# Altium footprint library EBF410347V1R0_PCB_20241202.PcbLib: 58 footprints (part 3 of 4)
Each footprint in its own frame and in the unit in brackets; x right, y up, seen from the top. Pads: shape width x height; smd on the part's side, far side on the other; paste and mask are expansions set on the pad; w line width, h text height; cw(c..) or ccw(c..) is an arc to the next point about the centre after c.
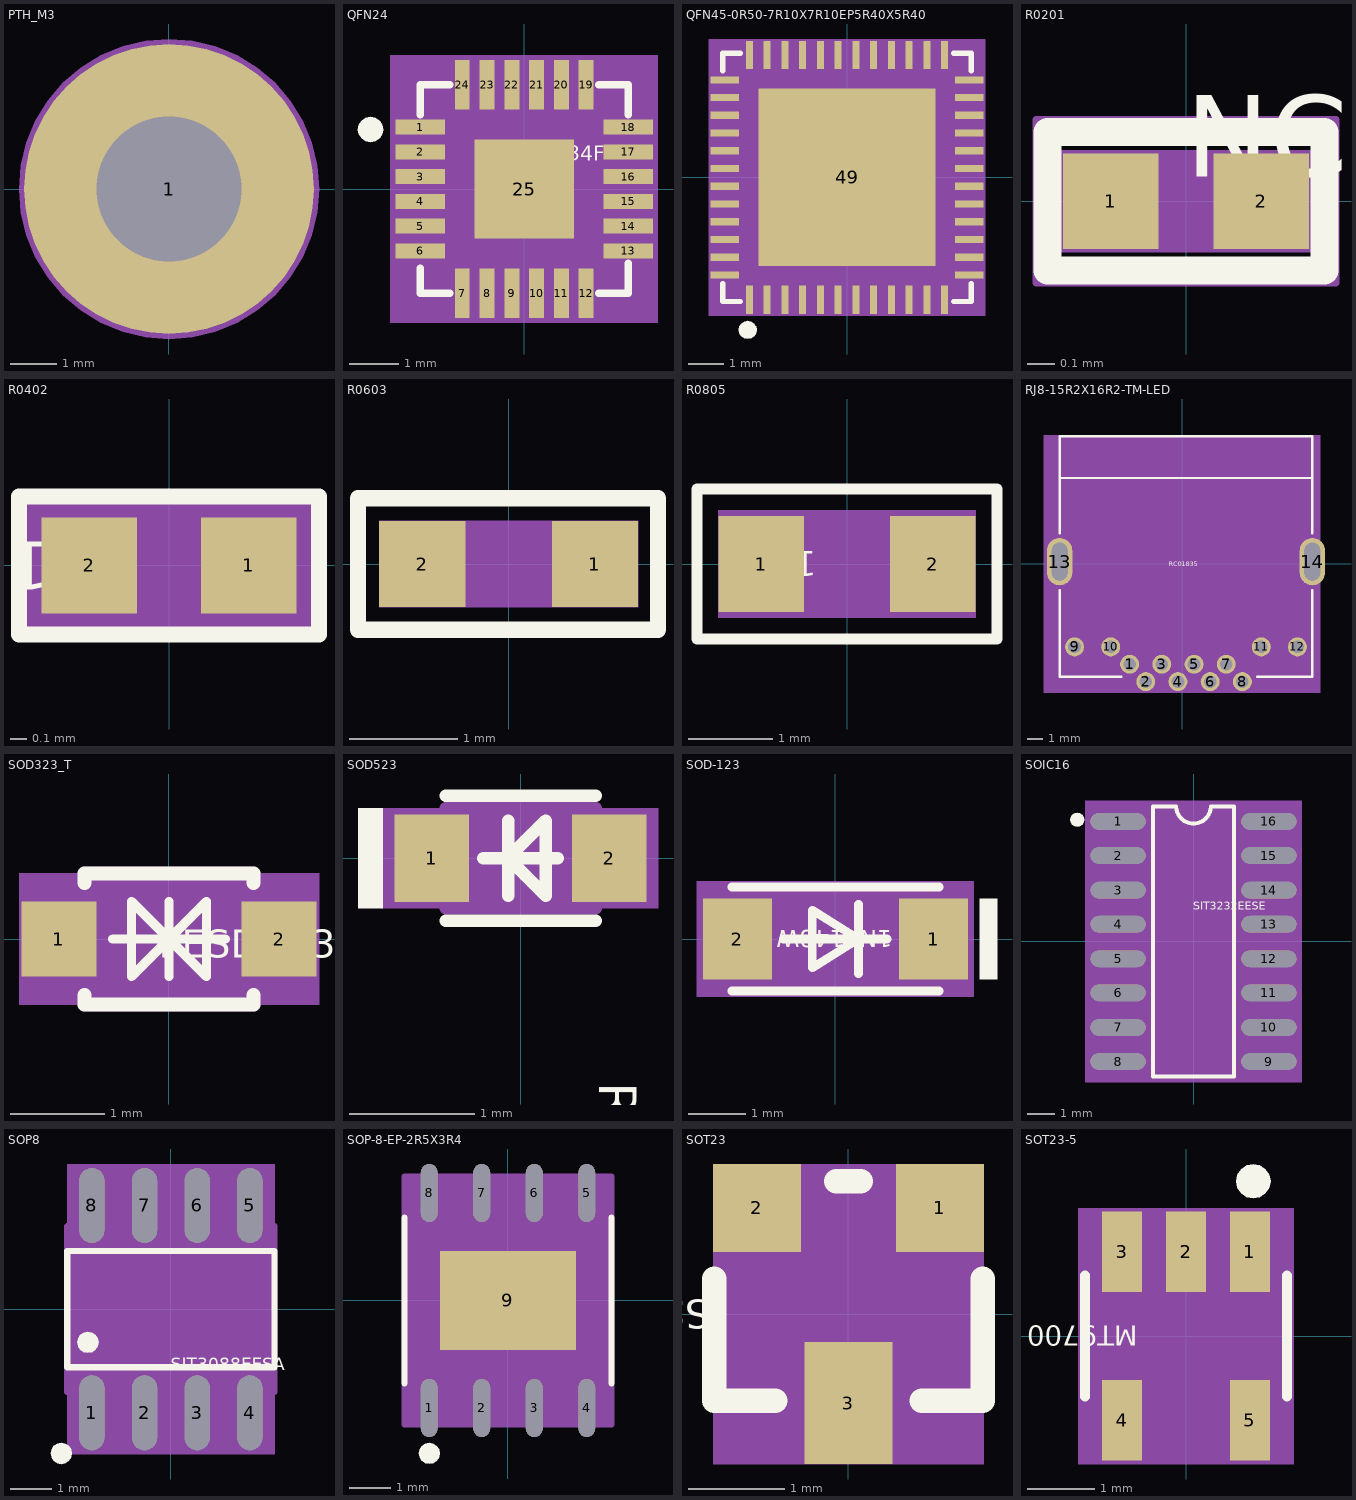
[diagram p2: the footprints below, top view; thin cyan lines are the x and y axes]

## PTH_M3 [mm] "PTH_M3"
pads (1):
  round 6.2 hole 3.1: 1(0,0)
Top Overlay:
  text "PTH_M3" at -0.72,-0.15 h0.3
Top 3D Body:
  region: 3.21,0 3.17,0.502 3.053,0.992 2.86,1.457 2.597,1.887 2.27,2.27 1.887,2.597 1.457,2.86 0.992,3.053 0.502,3.17 0,3.21 -0.502,3.17 -0.992,3.053 -1.457,2.86 -1.601,2.772 -1.887,2.597 -2.27,2.27 -2.597,1.887 -2.86,1.457 -3.053,0.992 -3.17,0.502 -3.21,0 -3.17,-0.502 -3.053,-0.992 -2.86,-1.457 -2.597,-1.887 -2.27,-2.27 -1.887,-2.597 -1.601,-2.772 -1.457,-2.86 -0.992,-3.053 -0.502,-3.17 0,-3.21 0.502,-3.17 0.992,-3.053 1.457,-2.86 1.887,-2.597 2.27,-2.27 2.597,-1.887 2.86,-1.457 3.053,-0.992 3.17,-0.502
Mechanical 14:
  text "1" at -0.254,0 h0.64
3D body: height 3.81, standoff 0, extent -3.21,-3.21 3.21,3.21

## QFN24 [mm] "QFN24"
pads (25):
  rect 1x0.3 smd: 1(-2.1,1.25) 2(-2.1,0.75) 3(-2.1,0.25) 4(-2.1,-0.25) 5(-2.1,-0.75) 6(-2.1,-1.25) 13(2.1,-1.25) 14(2.1,-0.75) 15(2.1,-0.25) 16(2.1,0.25) 17(2.1,0.75) 18(2.1,1.25)
  rect 0.3x1 smd: 7(-1.25,-2.1) 8(-0.75,-2.1) 9(-0.25,-2.1) 10(0.25,-2.1) 11(0.75,-2.1) 12(1.25,-2.1) 19(1.25,2.1) 20(0.75,2.1) 21(0.25,2.1) 22(-0.25,2.1) 23(-0.75,2.1) 24(-1.25,2.1)
  rect 2x2 smd: 25(0,0)
Top Overlay:
  dashed: -3.1,0.945 -3.002,0.965 -2.92,1.02 -2.865,1.102 -2.845,1.2 -2.865,1.298 -2.883,1.325 -2.92,1.38 -3.002,1.435 -3.1,1.455 -3.198,1.435 -3.28,1.38 -3.317,1.325 -3.335,1.298 -3.355,1.2 -3.335,1.102 -3.28,1.02 -3.198,0.965
  lines w0.15: -2.1,-1.6 -2.1,-2.1 -1.5,-2.1 ; -2.1,1.5 -2.1,2.1 -1.5,2.1 ; 1.5,-2.1 2.1,-2.1 2.1,-1.5 ; 1.5,2.1 2.1,2.1 2.1,1.5
  text "CH334F" at 0,0.57 h0.3
Top 3D Body:
  region: -2.7,-2.7 2.7,-2.7 2.7,2.7 -2.7,2.7
Mechanical 14:
  text "25" at 0,0.325 h0.41
  text "11" at 0.75,-1.775 h0.41
  text "12" at 1.25,-1.775 h0.41
  text "16" at 2.1,0.575 h0.41
  text "18" at 2.1,1.575 h0.41
  text "15" at 2.1,0.075 h0.41
  text "14" at 2.1,-0.425 h0.41
  text "6" at -2.1,-1.087 h0.41
  text "1" at -2.1,1.412 h0.41
  text "20" at 0.75,2.425 h0.41
  text "3" at -2.1,0.412 h0.41
  text "5" at -2.1,-0.588 h0.41
  text "13" at 2.1,-0.925 h0.41
  text "17" at 2.1,1.075 h0.41
  text "4" at -2.1,-0.087 h0.41
  text "7" at -1.25,-1.938 h0.41
  text "8" at -0.75,-1.938 h0.41
  text "10" at 0.25,-1.775 h0.41
  text "9" at -0.25,-1.938 h0.41
  text "19" at 1.25,2.425 h0.41
  text "2" at -2.1,0.913 h0.41
  text "24" at -1.25,2.425 h0.41
  text "23" at -0.75,2.425 h0.41
  text "22" at -0.25,2.425 h0.41
  text "21" at 0.25,2.425 h0.41
Top Assembly:
  lines w0.2: -2.05,-2.05 -2.05,2.05 2.05,2.05 2.05,-2.05 -2.05,-2.05
3D body: height 3.81, standoff 0, extent -2.7,-2.7 2.7,2.7

## QFN45-0R50-7R10X7R10EP5R40X5R40 [mm] "QFN45-0R50-7R10X7R10EP5R40X5R40"
pads (49):
  rect 0.2x0.8 smd: 1(-2.75,-3.45) 2(-2.25,-3.45) 3(-1.75,-3.45) 4(-1.25,-3.45) 5(-0.75,-3.45) 6(-0.25,-3.45) 7(0.25,-3.45) 8(0.75,-3.45) 9(1.25,-3.45) 10(1.75,-3.45) 11(2.25,-3.45) 12(2.75,-3.45) 25(2.75,3.45) 26(2.25,3.45) 27(1.75,3.45) 28(1.25,3.45) 29(0.75,3.45) 30(0.25,3.45) 31(-0.25,3.45) 32(-0.75,3.45) 33(-1.25,3.45) 34(-1.75,3.45) 35(-2.25,3.45) 36(-2.75,3.45)
  rect 0.8x0.2 smd: 13(3.45,-2.75) 14(3.45,-2.25) 15(3.45,-1.75) 16(3.45,-1.25) 17(3.45,-0.75) 18(3.45,-0.25) 19(3.45,0.25) 20(3.45,0.75) 21(3.45,1.25) 22(3.45,1.75) 23(3.45,2.25) 24(3.45,2.75) 37(-3.45,2.75) 38(-3.45,2.25) 39(-3.45,1.75) 40(-3.45,1.25) 41(-3.45,0.75) 42(-3.45,0.25) 43(-3.45,-0.25) 44(-3.45,-0.75) 45(-3.45,-1.25) 46(-3.45,-1.75) 47(-3.45,-2.25) 48(-3.45,-2.75)
  rect 5x5 smd: 49(0,0)
Top Overlay:
  dashed: -2.8,-4.555 -2.702,-4.535 -2.62,-4.48 -2.564,-4.398 -2.545,-4.3 -2.564,-4.202 -2.583,-4.175 -2.62,-4.12 -2.702,-4.064 -2.8,-4.045 -2.898,-4.064 -2.98,-4.12 -3.017,-4.175 -3.036,-4.202 -3.055,-4.3 -3.036,-4.398 -2.98,-4.48 -2.898,-4.535
  lines w0.15: -3.5,-3 -3.5,-3.5 -3,-3.5 ; -3.5,3 -3.5,3.5 -3,3.5 ; 3,-3.5 3.5,-3.5 3.5,-3 ; 3,3.5 3.5,3.5 3.5,3
  text "GM8775C" at 0,0.69 h0.3
Top 3D Body:
  region: -3.9,3.9 -3.9,-3.9 3.9,-3.9 3.9,3.9
Mechanical 14:
  text "5" at -0.75,-3.348 h0.25
  text "37" at -3.324,3.156 h0.25
  text "9" at 1.25,-3.348 h0.25
  text "49" at 0,0.203 h0.25
  text "21" at 3.576,1.656 h0.25
  text "17" at 3.576,-0.344 h0.25
  text "16" at 3.576,-0.944 h0.25
  text "43" at -3.324,0.156 h0.25
  text "12" at 2.75,-3.247 h0.25
  text "29" at 0.75,3.653 h0.25
  text "28" at 1.25,3.653 h0.25
  text "8" at 0.75,-3.348 h0.25
  text "7" at 0.25,-3.348 h0.25
  text "30" at 0.25,3.653 h0.25
  text "45" at -3.324,-0.844 h0.25
  text "15" at 3.576,-1.344 h0.25
  text "31" at -0.25,3.653 h0.25
  text "47" at -3.324,-1.944 h0.25
  text "40" at -3.324,1.556 h0.25
  text "24" at 3.576,3.056 h0.25
  text "2" at -2.25,-3.348 h0.25
  text "11" at 2.25,-3.247 h0.25
  text "32" at -0.75,3.653 h0.25
  text "25" at 2.75,3.653 h0.25
  text "14" at 3.576,-1.844 h0.25
  text "18" at 3.576,0.156 h0.25
  text "42" at -3.324,0.656 h0.25
  text "34" at -1.75,3.653 h0.25
  text "19" at 3.576,0.656 h0.25
  text "44" at -3.324,-0.344 h0.25
  text "22" at 3.576,2.056 h0.25
  text "46" at -3.324,-1.344 h0.25
  text "20" at 3.576,1.156 h0.25
  text "23" at 3.576,2.656 h0.25
  text "39" at -3.324,2.056 h0.25
  text "33" at -1.25,3.653 h0.25
  text "35" at -2.25,3.653 h0.25
  text "36" at -2.75,3.653 h0.25
  text "38" at -3.324,2.556 h0.25
  text "41" at -3.324,1.156 h0.25
  text "13" at 3.5,-2.394 h0.25
  text "10" at 1.75,-3.247 h0.25
  text "27" at 1.75,3.653 h0.25
  text "1" at -2.75,-3.348 h0.25
  text "26" at 2.25,3.653 h0.25
  text "48" at -3.324,-2.344 h0.25
  text "6" at -0.25,-3.348 h0.25
  text "4" at -1.25,-3.348 h0.25
  text "3" at -1.75,-3.348 h0.25
Top Assembly:
  lines w0.15: -3.5,-3.5 3.5,-3.5 3.5,3.5 -3.5,3.5 -3.5,-3.5
3D body: height 3.81, standoff 0, extent -3.9,-3.9 3.9,3.9

## R0201 [mm] "R0201"
pads (2):
  rect 0.35x0.35 smd: 1(-0.275,0) 2(0.275,0)
Top Overlay:
  lines w0.102: -0.508,-0.254 0.508,-0.254 0.508,0.254 -0.508,0.254 -0.508,-0.254
  text ".Designator" at 0,0.33 h0.3
  text "NC" at 0,0.09 h0.3
Top 3D Body:
  region: -0.475,-0.175 0.475,-0.175 0.475,0.175 -0.475,0.175
Mechanical 14:
  text "1" at -0.275,0.203 h0.51
  text "2" at 0.275,0.203 h0.51
Top Assembly:
  lines w0.025: -0.55,-0.3 -0.55,0.3 0.55,0.3 0.55,-0.3 -0.55,-0.3 ; -0.475,-0.175 0.475,-0.175 0.475,0.175 -0.475,0.175 -0.475,-0.175
  text "NC" at 0,0 h0.51
3D body: height 3.81, standoff 0, extent -0.475,-0.175 0.475,0.175

## R0402 [mm] "R0402"
pads (2):
  rect 0.599x0.599 smd: 1(0.5,0) 2(-0.5,0)
Top Overlay:
  lines w0.102: -0.94,-0.432 0.94,-0.432 0.94,0.432 -0.94,0.432 -0.94,-0.432
  text "115K" at -0.48,0.15 h0.3
Top 3D Body:
  region: -0.94,-0.432 -0.94,0.432 0.94,0.432 0.94,-0.432
Mechanical 14:
  text "2" at -0.957,0 h1.14
  text "1" at 0.043,0 h1.14
Top Assembly:
  dashed: 0.94,0.432 0.94,-0.432 -0.94,-0.432 -0.94,0.432
3D body: height 3.81, standoff 0, extent -0.94,-0.432 0.94,0.432

## R0603 [mil] "R0603"
pads (2):
  rect 31.5x31.5 smd: 1(31.5,0) 2(-31.5,0)
Top Overlay:
  lines w6: -55,-24 54.5,-24 54.5,24 -55,24 -55,-24
  text "10K" at -14.17,5.91 h11.81
Top 3D Body:
  region: 47.24,15.75 47.24,-15.75 -47.24,-15.75 -47.24,15.75
Mechanical 14:
  text "2" at -45.5,0 h35
  text "1" at 17.5,0 h35
3D body: height 150, standoff 0, extent -47.24,-15.75 47.24,15.75

## R0805 [mil] "R0805"
pads (2):
  rect 40x45 smd: 1(-40,0) 2(40,0)
Top Overlay:
  lines w5: -70,-35 70,-35 70,35 -70,35 -70,-35
  text "10R" at -14.17,5.91 h11.81
Top 3D Body:
  region: -60,25 60,25 60,-25 -60,-25
Mechanical 14:
  text "1" at -48,0 h20
  text "2" at 32,0 h20
3D body: height 150, standoff 0, extent -60,-25 60,25

## RJ8-15R2X16R2-TM-LED [mm] "RJ8-15R2X16R2-TM-LED"
pads (14):
  round 1.2 hole 0.8: 1(-3.32,-6.35) 2(-2.3,-7.45) 3(-1.28,-6.35) 4(-0.26,-7.45) 5(0.76,-6.35) 6(1.78,-7.45) 7(2.8,-6.35) 8(3.82,-7.45) 9(-6.81,-5.25) 10(-4.52,-5.25) 11(5.02,-5.25) 12(7.31,-5.25)
  oval 1.6x3 hole 2.4 slot 1 at 0 deg: 13(-7.75,0.15) 14(8.25,0.15)
Top Overlay:
  lines w0.15: -7.75,-1.65 -7.75,-7.15 -3.85,-7.15 ; 4.75,-7.15 8.25,-7.15 8.25,-1.65 ; -7.75,1.95 -7.75,8.1 8.25,8.1 8.25,1.95 8.25,5.45 -7.75,5.45 -7.75,1.95
  text "RC01835" at -0.84,-0.15 h0.3
Top 3D Body:
  region: -8.75,8.15 -8.75,-8.15 8.75,-8.15 8.75,8.15
Mechanical 14:
  text "11" at 4.512,-5.25 h0.64
  text "10" at -5.028,-5.25 h0.64
  text "9" at -7.064,-5.25 h0.64
  text "14" at 7.234,0.15 h0.64
  text "13" at -8.766,0.15 h0.64
  text "12" at 6.802,-5.25 h0.64
  text "2" at -2.554,-7.45 h0.64
  text "3" at -1.534,-6.35 h0.64
  text "4" at -0.514,-7.45 h0.64
  text "6" at 1.526,-7.45 h0.64
  text "1" at -3.574,-6.35 h0.64
  text "8" at 3.566,-7.45 h0.64
  text "5" at 0.506,-6.35 h0.64
  text "7" at 2.546,-6.35 h0.64
3D body: height 3.81, standoff 0, extent -8.75,-8.15 8.75,8.15

## SOD323_T [mil] "SOD323_T"
pads (2):
  rect 31.5x31.5 smd: 1(-46.26,0) 2(46.26,0)
Top Overlay:
  lines w3.94: -23.62,0 23.62,0 ; 0,-15.75 0,15.75 ; 0,0 -15.75,-15.75 -15.75,15.75 0,0 ; 0,0 15.75,15.75 15.75,-15.75 0,0
  lines w5.91: -35.43,-23.62 -35.43,-27.56 35.43,-27.56 35.43,-23.62 ; -35.43,23.62 -35.43,27.56 35.43,27.56 35.43,23.62
  text "PESD3V3L1BA" at -4.37,-7.87 h11.81
Top 3D Body:
  region: -62.99,27.56 -62.99,-27.56 62.99,-27.56 62.99,27.56
Mechanical 14:
  text "1" at -46.26,-10 h25
  text "2" at 46.26,-10 h25
Top Assembly:
  lines w5.91: -35.43,-27.56 35.43,-27.56 35.43,27.56 -35.43,27.56 -35.43,-27.56
3D body: height 150, standoff 0, extent -62.99,-27.56 62.99,27.56

## SOD523 [mm] "SOD523"
pads (2):
  rect 0.6x0.7 smd: 1(-0.71,0) 2(0.71,0)
Top Overlay:
  dashed: -1.3,0.4 -1.3,-0.4 -1.1,-0.4 -1.1,0.4
  lines w0.1: -0.6,-0.5 0.6,-0.5 ; -0.6,0.5 0.6,0.5 ; -0.3,0 0.3,0 ; -0.1,-0.3 -0.1,0.3 ; -0.1,0 0.2,0.3 0.2,-0.3 -0.1,0
  text "RB521S-30" at 0.628,-1.794 h0.3
Top 3D Body:
  region: -1.1,0.4 -1.1,-0.4 1.1,-0.4 1.1,0.4
Mechanical 14:
  text "2" at 0.71,-0.254 h0.64
  text "1" at -0.71,-0.254 h0.64
Top Assembly:
  lines w0.1: -0.6,-0.4 0.6,-0.4 0.6,0.4 -0.6,0.4 -0.6,-0.4
3D body: height 3.81, standoff 0, extent -1.1,-0.4 1.1,0.4

## SOD-123 [mm] "SOD-123"
pads (2):
  rect 1.2x1.4 smd: 1(1.7,0) 2(-1.7,0)
Top Overlay:
  dashed: 2.5,0.7 2.5,-0.7 2.8,-0.7 2.8,0.7
  lines w0.15: -1.8,-0.9 1.8,-0.9 ; -1.8,0.9 1.8,0.9 ; -0.9,0 0.9,0 ; 0.4,-0.6 0.4,0.6 ; -0.4,-0.5 -0.4,0.5 0.4,0 -0.4,-0.5
  text "1N4148W" at 0.986,0.15 h0.3
Top 3D Body:
  region: -2.4,-1 2.4,-1 2.4,1 -2.4,1
Mechanical 14:
  text "2" at -2.015,0 h0.79
  text "1" at 1.385,0 h0.79
Top Assembly:
  lines w0.15: -1.8,-0.9 1.8,-0.9 1.8,0.9 -1.8,0.9 -1.8,-0.9
3D body: height 3.81, standoff 0, extent -2.4,-1 2.4,1

## SOIC16 [mil] "SOIC16"
pads (16):
  oval 80x24 smd: 1(-109.8,174.8) 2(-109.8,125.2) 3(-109.8,74.8) 4(-109.8,25.2) 5(-109.8,-25.2) 6(-109.8,-74.8) 7(-109.8,-125.2) 8(-109.8,-174.8) 9(109.8,-174.8) 10(109.8,-125.2) 11(109.8,-74.8) 12(109.8,-25.2) 13(109.8,25.2) 14(109.8,74.8) 15(109.8,125.2) 16(109.8,174.8)
Top Overlay:
  dashed: -169.29,167.13 -165.45,167.89 -162.2,170.07 -160.02,173.32 -159.26,177.16 -160.02,181.01 -160.75,182.1 -162.2,184.26 -165.45,186.44 -169.29,187.2 -173.13,186.44 -176.39,184.26 -177.83,182.1 -178.56,181.01 -179.33,177.16 -178.56,173.32 -176.39,170.07 -173.13,167.89
  lines w5.91: -59.05,-196.85 -59.05,196.85 -39.37,196.85 -25.2,196.85 ccw(c0,196.85) 25.2,196.85 59.05,196.85 59.05,-196.85 -59.05,-196.85
  text "SIT3232EESE" at -0.01,46.06 h11.81
Top 3D Body:
  region: -157.48,204.72 -157.48,-204.72 157.48,-204.72 157.48,204.72
Mechanical 14:
  text "14" at 109.8,122.8 h60
  text "15" at 109.8,173.2 h60
  text "11" at 109.8,-26.8 h60
  text "12" at 109.8,22.8 h60
  text "10" at 109.8,-77.2 h60
  text "9" at 109.8,-150.8 h60
  text "1" at -109.8,198.8 h60
  text "4" at -109.8,49.2 h60
  text "3" at -109.8,98.8 h60
  text "2" at -109.8,149.2 h60
  text "5" at -109.8,-1.2 h60
  text "6" at -109.8,-50.8 h60
  text "13" at 109.8,73.2 h60
  text "7" at -109.8,-101.2 h60
  text "8" at -109.8,-150.8 h60
  text "16" at 109.8,222.8 h60
3D body: height 150, standoff 0, extent -157.48,-204.72 157.48,204.72

## SOP8 [mm] "SOP8"
pads (8):
  oval 0.6x1.8 smd: 1(-1.905,-2.5) 2(-0.635,-2.5) 3(0.635,-2.5) 4(1.905,-2.5) 5(1.905,2.5) 6(0.635,2.5) 7(-0.635,2.5) 8(-1.905,2.5)
Top Overlay:
  dashed: -2.642,-3.225 -2.544,-3.244 -2.461,-3.3 -2.406,-3.382 -2.387,-3.48 -2.406,-3.577 -2.425,-3.605 -2.461,-3.66 -2.544,-3.715 -2.642,-3.735 -2.739,-3.715 -2.822,-3.66 -2.859,-3.605 -2.877,-3.577 -2.896,-3.48 -2.877,-3.382 -2.822,-3.3 -2.739,-3.244
  dashed: -2,-0.545 -1.902,-0.565 -1.82,-0.62 -1.765,-0.702 -1.745,-0.8 -1.765,-0.898 -1.783,-0.925 -1.82,-0.98 -1.902,-1.035 -2,-1.055 -2.098,-1.035 -2.18,-0.98 -2.217,-0.925 -2.235,-0.898 -2.255,-0.8 -2.235,-0.702 -2.18,-0.62 -2.098,-0.565
  lines w0.15: -2.5,-1.4 2.5,-1.4 2.5,1.4 -2.5,1.4 -2.5,-1.4
  text "SIT3088EESA" at 0,-1.47 h0.3
Top 3D Body:
  region: -2.5,3.5 -2.5,-3.5 2.5,-3.5 2.5,3.5
Mechanical 14:
  text "5" at 1.905,2.246 h0.64
  text "4" at 1.905,-2.754 h0.64
  text "2" at -0.635,-2.754 h0.64
  text "3" at 0.635,-2.754 h0.64
  text "8" at -1.905,2.246 h0.64
  text "6" at 0.635,2.246 h0.64
  text "7" at -0.635,2.246 h0.64
  text "1" at -1.905,-2.754 h0.64
Top Assembly:
  lines w0.15: -2.5,-2 2.5,-2 2.5,2 -2.5,2 -2.5,-2
3D body: height 3.81, standoff 0, extent -2.5,-3.5 2.5,3.5

## SOP-8-EP-2R5X3R4 [mm] "SOP-8-EP-2R5X3R4"
pads (9):
  oval 0.4x1.4 smd: 1(-1.905,-2.6) 2(-0.635,-2.6) 3(0.635,-2.6) 4(1.905,-2.6) 5(1.905,2.6) 6(0.635,2.6) 7(-0.635,2.6) 8(-1.905,2.6)
  rect 3.3x2.4 smd: 9(0,0)
Top Overlay:
  dashed: -1.645,-3.7 -1.664,-3.602 -1.72,-3.52 -1.802,-3.464 -1.9,-3.445 -1.998,-3.464 -2.025,-3.483 -2.08,-3.52 -2.136,-3.602 -2.155,-3.7 -2.136,-3.798 -2.08,-3.88 -2.025,-3.917 -1.998,-3.935 -1.9,-3.955 -1.802,-3.935 -1.72,-3.88 -1.664,-3.798
  lines w0.15: -2.5,-2 -2.5,2 ; 2.5,-2 2.5,2
  text "NS4110B" at -0.84,-0.15 h0.3
Top 3D Body:
  region: -2.5,3 -2.5,-3 2.5,-3 2.5,3
Mechanical 14:
  text "9" at -0.254,0 h0.64
  text "7" at -0.889,2.6 h0.64
  text "8" at -2.159,2.6 h0.64
  text "4" at 1.651,-2.6 h0.64
  text "6" at 0.381,2.6 h0.64
  text "2" at -0.889,-2.6 h0.64
  text "5" at 1.651,2.6 h0.64
  text "1" at -2.159,-2.6 h0.64
  text "3" at 0.381,-2.6 h0.64
Top Assembly:
  lines w0.15: -2.5,-3 2.5,-3 2.5,3 -2.5,3 -2.5,-3
3D body: height 3.81, standoff 0, extent -2.5,-3 2.5,3

## SOT23 [mil] "SOT23"
pads (3):
  rect 36x36 smd: 1(37.5,43.5) 2(-37.5,43.5)
  rect 36x50 smd: 3(0,-36.5)
Top Overlay:
  lines w10: -55,14.5 -55,-35.5 -30,-35.5 ; -5,54.5 5,54.5 ; 30,-35.5 55,-35.5 55,14.5
  text "SSM3J328R-LF" at -56.69,5.91 h11.81
Top 3D Body:
  region: 55.5,61.5 55.5,-61.5 -55.5,-61.5 -55.5,61.5
Mechanical 14:
  text "3" at -14,-36.5 h35
  text "2" at -51.5,43.5 h35
  text "1" at 23.5,43.5 h35
3D body: height 150, standoff 0, extent -55.5,-61.5 55.5,61.5

## SOT23-5 [mm] "SOT23-5"
pads (5):
  rect 0.599x1.199 smd: 1(0.95,1.25) 2(0,1.25) 3(-0.95,1.25) 4(-0.95,-1.25) 5(0.95,-1.25)
Top Overlay:
  dashed: 1.255,2.3 1.235,2.202 1.18,2.12 1.098,2.065 1,2.045 0.902,2.065 0.875,2.083 0.82,2.12 0.765,2.202 0.745,2.3 0.765,2.398 0.82,2.48 0.875,2.517 0.902,2.535 1,2.555 1.098,2.535 1.18,2.48 1.235,2.398
  lines w0.15: -1.5,-0.9 -1.5,0.9 ; 1.5,-0.9 1.5,0.9
  text "MT9700" at -0.72,0.15 h0.3
Top 3D Body:
  region: 1.6,-1.9 1.6,1.9 -1.6,1.9 -1.6,-1.9
Mechanical 14:
  text "2" at -0.152,1.25 h0.38
  text "5" at 0.798,-1.25 h0.38
  text "4" at -1.102,-1.25 h0.38
  text "3" at -1.102,1.25 h0.38
  text "1" at 0.798,1.25 h0.38
Top Assembly:
  lines w0.15: -1.5,-0.85 -1.5,0.85 1.5,0.85 1.5,-0.85 -1.5,-0.85
3D body: height 3.81, standoff 0, extent -1.6,-1.9 1.6,1.9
